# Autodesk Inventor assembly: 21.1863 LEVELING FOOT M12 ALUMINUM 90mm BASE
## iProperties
Created: 2007-03
Part Number: 21.1863 LEVELING FOOT M12 ALUMINUM 90mm BASE
Document SubType Name: Assembly
Designer: Andy Moles
Author: Andy Moles
